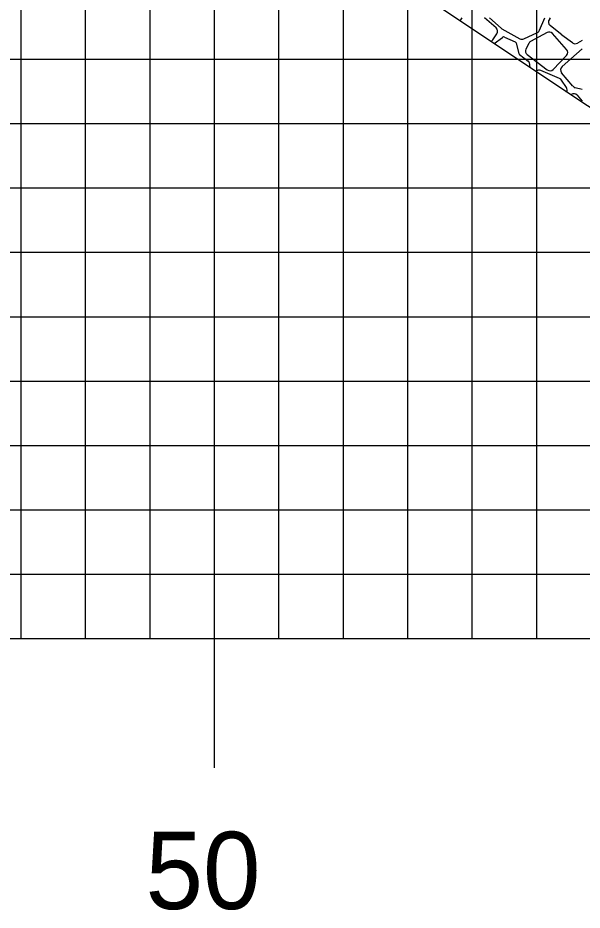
# Model space of a CAD drawing. Extents: x 1770055 to 1770398, y 442591 to 442811.
# Drawn here: x 1770167.48 to 1770176.23, y 442679.45 to 442693.31 of the extents above; entities that cross this region are included whole.
import ezdxf

# ---------------------------------------------------------------- set-up
doc = ezdxf.new("R2010")
doc.units = 0
for name, color, linetype in [('ANNOTATION', 7, 'Continuous'), ('GRUBBING IN FILL', 7, 'Continuous'), ('H_V ANNOTATION', 7, 'Continuous'), ('MAJOR', 7, 'Continuous'), ('MINOR', 7, 'Continuous')]:
    doc.layers.add(name, color=color, linetype=linetype)

msp = doc.modelspace()

# ---------------------------------------------------------------- linework, layer by layer
at = {"layer": 'ANNOTATION'}
msp.add_lwpolyline([(1770184.461, 442686.509), (1770130.169, 442722.703), (1770129.162, 442723.293), (1770128.291, 442723.662), (1770127.48, 442723.874), (1770126.762, 442723.946)], dxfattribs=at)
at = {"layer": 'GRUBBING IN FILL'}
for p, q in [((1770174.275, 442693.299), (1770174.284, 442693.307)), ((1770174.365, 442693.307), (1770174.334, 442693.26)), ((1770174.898, 442693.149), (1770174.717, 442693.307)), ((1770174.794, 442693.307), (1770174.975, 442693.145)), ((1770175.571, 442693.115), (1770175.654, 442693.307)), ((1770175.724, 442693.283), (1770175.742, 442693.307)), ((1770174.987, 442693.136), (1770175.267, 442692.983)), ((1770175.795, 442693.14), (1770175.735, 442693.188)), ((1770175.915, 442693.042), (1770175.795, 442693.139)), ((1770174.846, 442692.965), (1770174.909, 442693.059)), ((1770174.868, 442692.908), (1770174.995, 442693.003)), ((1770175.029, 442693.007), (1770175.192, 442692.935)), ((1770175.329, 442692.981), (1770175.538, 442693.08)), ((1770175.687, 442693.078), (1770175.433, 442692.938)), ((1770175.992, 442692.817), (1770175.771, 442693.064)), ((1770176.083, 442692.917), (1770175.917, 442693.04)), ((1770175.211, 442692.912), (1770175.249, 442692.755)), ((1770175.405, 442692.909), (1770175.36, 442692.82)), ((1770176.232, 442692.957), (1770176.158, 442692.914)), ((1770175.262, 442692.736), (1770175.397, 442692.636)), ((1770175.38, 442692.735), (1770175.691, 442692.497)), ((1770175.782, 442692.505), (1770175.991, 442692.724)), ((1770175.921, 442692.549), (1770176.232, 442692.823)), ((1770175.411, 442692.614), (1770175.423, 442692.534)), ((1770175.522, 442692.482), (1770175.512, 442692.474)), ((1770175.883, 442692.365), (1770175.59, 442692.49)), ((1770176.09, 442692.243), (1770175.913, 442692.454)), ((1770175.988, 442692.225), (1770175.914, 442692.34)), ((1770176.232, 442692.192), (1770176.125, 442692.22)), ((1770176.058, 442692.111), (1770176.062, 442692.114)), ((1770176.157, 442692.104), (1770176.232, 442692.013))]:
    msp.add_line(p, q, dxfattribs=at)
for centre, major_axis, start_param, end_param in [((1770175.777, 442693.241), (0, -0.0683), 4.048343, 5.608444), ((1770174.853, 442693.098), (0, -0.0683), 0.977446, 2.424153), ((1770175.02, 442693.196), (0, -0.0683), 5.554357, 5.782172), ((1770175.752, 442693.086), (0, 0.0683), 5.600869, 5.608444), ((1770175.015, 442692.976), (0, 0.0342), 5.866747, 6.924845), ((1770175.3, 442693.043), (0, -0.0683), 5.782172, 6.726567), ((1770175.509, 442693.142), (0, -0.0683), 0.443382, 1.163165), ((1770175.72, 442693.018), (0, 0.0683), 5.44252, 6.785098), ((1770175.958, 442693.095), (0, -0.0683), 5.600869, 5.645637), ((1770174.789, 442693.004), (0, -0.0683), 0.367617, 0.977446), ((1770174.766, 442693.045), (0, -0.171), 0.619639, 0.641659), ((1770175.178, 442692.904), (0, 0.0342), 4.95256, 5.866747), ((1770175.466, 442692.879), (0, 0.0683), 0.501913, 1.108164), ((1770176.124, 442692.972), (0, -0.0683), 5.645637, 6.81814), ((1770175.282, 442692.763), (0, -0.0342), 4.95256, 5.649393), ((1770175.421, 442692.79), (0, 0.0683), 1.108164, 2.48948), ((1770175.941, 442692.771), (0, -0.0683), 0.810393, 2.300927), ((1770175.377, 442692.609), (0, 0.0342), 4.865038, 5.649393), ((1770175.563, 442692.427), (0, 0.0683), 5.881372, 6.922099), ((1770175.733, 442692.552), (0, -0.0683), 5.631073, 7.093578), ((1770175.966, 442692.498), (0, -0.0683), 3.861663, 5.40978), ((1770175.856, 442692.302), (0, 0.0683), 5.287694, 5.881372), ((1770175.931, 442692.187), (0, -0.0683), 1.079941, 2.146101), ((1770176.143, 442692.287), (0, -0.0683), 5.40978, 6.025862), ((1770176.104, 442692.061), (0, 0.0683), 5.401291, 6.952921)]:
    msp.add_ellipse(centre, major_axis=major_axis, ratio=0.99895, start_param=start_param, end_param=end_param, dxfattribs=at)
at = {"layer": 'MAJOR'}
for p, q in [((1770170.528, 442683.665), (1770170.528, 442733.665)), ((1770080.528, 442688.665), (1770360.528, 442688.665)), ((1770080.528, 442683.665), (1770360.528, 442683.665)), ((1770080.528, 442683.665), (1770360.528, 442683.665)), ((1770170.528, 442681.661), (1770170.528, 442683.665))]:
    msp.add_line(p, q, dxfattribs=at)
at = {"layer": 'MINOR'}
for p, q in [((1770167.528, 442683.665), (1770167.528, 442733.665)), ((1770168.528, 442683.665), (1770168.528, 442733.665)), ((1770169.528, 442683.665), (1770169.528, 442733.665)), ((1770171.528, 442683.665), (1770171.528, 442733.665)), ((1770172.528, 442683.665), (1770172.528, 442733.665)), ((1770173.528, 442683.665), (1770173.528, 442733.665)), ((1770174.528, 442683.665), (1770174.528, 442733.665)), ((1770175.528, 442683.665), (1770175.528, 442733.665)), ((1770080.528, 442692.665), (1770360.528, 442692.665)), ((1770080.528, 442691.665), (1770360.528, 442691.665)), ((1770080.528, 442690.665), (1770360.528, 442690.665)), ((1770080.528, 442689.665), (1770360.528, 442689.665)), ((1770080.528, 442687.665), (1770360.528, 442687.665)), ((1770080.528, 442686.665), (1770360.528, 442686.665)), ((1770080.528, 442685.665), (1770360.528, 442685.665)), ((1770080.528, 442684.665), (1770360.528, 442684.665))]:
    msp.add_line(p, q, dxfattribs=at)

# ---------------------------------------------------------------- texts
at = {"layer": 'H_V ANNOTATION'}
msp.add_text('50', height=1.2, dxfattribs=at).set_placement((1770169.457, 442679.465))

doc.saveas('drawing.dxf')
